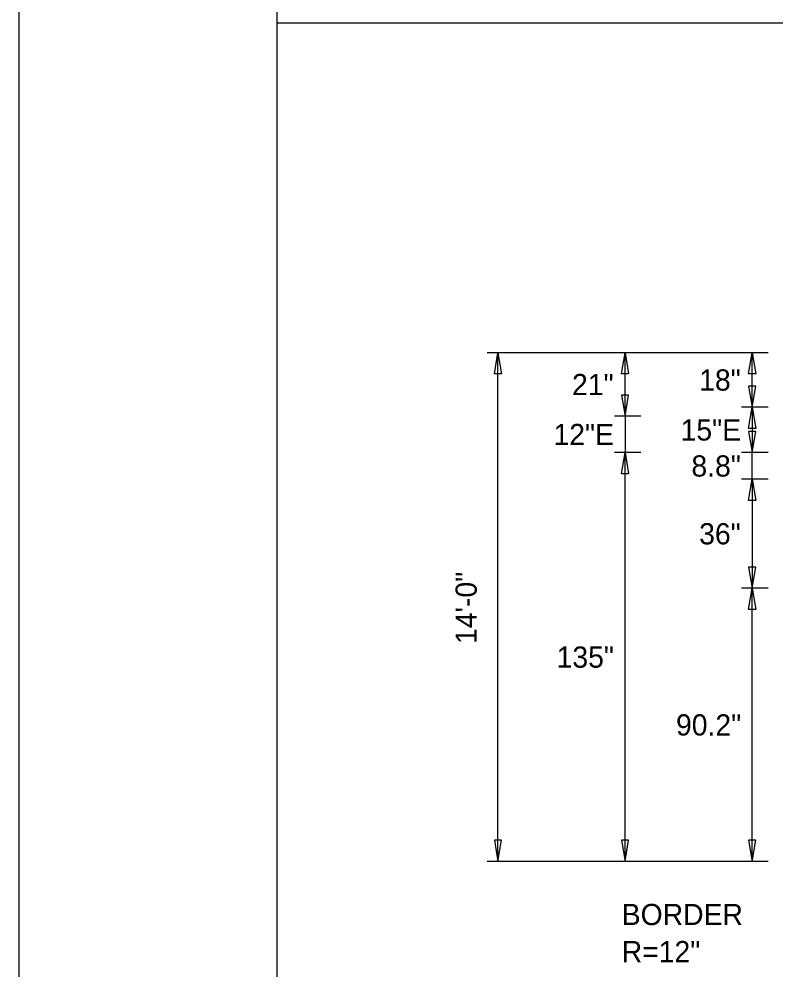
# Model space of a CAD drawing. Extents: x 2150010 to 2150174, y 145114 to 145224.
# Drawn here: x 2150010.46 to 2150031.3, y 145140.9 to 145167.07 of the extents above; entities that cross this region are included whole.
import ezdxf

# ---------------------------------------------------------------- set-up
doc = ezdxf.new("R2010")
doc.units = 0
for name, color, linetype in [('BORDER', 7, 'Continuous'), ('GSDIMS', 7, 'Continuous'), ('Level 1', 7, 'Continuous'), ('PDF', 7, 'Continuous')]:
    doc.layers.add(name, color=color, linetype=linetype)

msp = doc.modelspace()

# ---------------------------------------------------------------- linework, layer by layer
at = {"layer": 'BORDER'}
for p, q in [((2150010.458, 145219.948), (2150010.458, 145114.088)), ((2150017.557, 145216.512), (2150017.557, 145117.388))]:
    msp.add_line(p, q, dxfattribs=at)
at = {"layer": 'GSDIMS'}
for p, q in [((2150024.083, 145157.883), (2150023.353, 145157.883)), ((2150023.645, 145143.883), (2150023.645, 145157.883)), ((2150031.083, 145157.883), (2150024.083, 145157.883)), ((2150027.583, 145157.883), (2150026.853, 145157.883)), ((2150027.145, 145156.133), (2150027.145, 145157.883)), ((2150031.083, 145157.883), (2150030.353, 145157.883)), ((2150030.645, 145156.383), (2150030.645, 145157.883)), ((2150031.083, 145156.383), (2150030.353, 145156.383)), ((2150031.083, 145156.383), (2150030.353, 145156.383)), ((2150030.645, 145156.383), (2150030.645, 145155.133)), ((2150027.583, 145156.133), (2150026.853, 145156.133)), ((2150027.583, 145156.133), (2150026.853, 145156.133)), ((2150027.145, 145156.133), (2150027.145, 145155.133)), ((2150027.583, 145155.133), (2150026.853, 145155.133)), ((2150027.583, 145155.133), (2150026.853, 145155.133)), ((2150027.145, 145143.883), (2150027.145, 145155.133)), ((2150031.083, 145155.133), (2150030.353, 145155.133)), ((2150031.083, 145155.133), (2150030.353, 145155.133)), ((2150030.645, 145154.401), (2150030.645, 145155.133)), ((2150031.083, 145154.401), (2150030.353, 145154.401)), ((2150031.083, 145154.401), (2150030.353, 145154.401)), ((2150030.645, 145154.401), (2150030.645, 145151.401)), ((2150031.083, 145151.401), (2150030.353, 145151.401)), ((2150031.083, 145151.401), (2150030.353, 145151.401)), ((2150030.645, 145143.883), (2150030.645, 145151.401)), ((2150024.083, 145143.883), (2150023.353, 145143.883)), ((2150031.083, 145143.883), (2150024.083, 145143.883)), ((2150027.583, 145143.883), (2150026.853, 145143.883)), ((2150031.083, 145143.883), (2150030.353, 145143.883))]:
    msp.add_line(p, q, dxfattribs=at)
for points in [[(2150023.645, 145157.883), (2150023.742, 145157.3), (2150023.548, 145157.3)], [(2150027.145, 145157.883), (2150027.242, 145157.3), (2150027.048, 145157.3)], [(2150030.645, 145157.883), (2150030.742, 145157.3), (2150030.548, 145157.3)], [(2150030.645, 145156.383), (2150030.742, 145156.966), (2150030.548, 145156.966)], [(2150027.145, 145156.133), (2150027.242, 145156.716), (2150027.048, 145156.716)], [(2150030.645, 145156.383), (2150030.742, 145155.8), (2150030.548, 145155.8)], [(2150030.645, 145155.133), (2150030.742, 145155.716), (2150030.548, 145155.716)], [(2150027.145, 145155.133), (2150027.242, 145154.55), (2150027.048, 145154.55)], [(2150030.645, 145154.401), (2150030.742, 145153.818), (2150030.548, 145153.818)], [(2150030.645, 145151.401), (2150030.742, 145151.984), (2150030.548, 145151.984)], [(2150030.645, 145151.401), (2150030.742, 145150.818), (2150030.548, 145150.818)], [(2150023.645, 145143.883), (2150023.742, 145144.466), (2150023.548, 145144.466)], [(2150027.145, 145143.883), (2150027.242, 145144.466), (2150027.048, 145144.466)], [(2150030.645, 145143.883), (2150030.742, 145144.466), (2150030.548, 145144.466)]]:
    msp.add_lwpolyline(points, close=True, dxfattribs=at)
at = {"layer": 'Level 1'}
msp.add_line((2150135.447, 145166.95), (2150017.557, 145166.95), dxfattribs=at)
at = {"layer": 'PDF'}
msp.add_lwpolyline([(2150010.458, 145114.088), (2150174.061, 145114.088), (2150174.061, 145219.948), (2150010.458, 145219.948)], close=True, dxfattribs=at)

# ---------------------------------------------------------------- texts
at = {"layer": 'GSDIMS'}
for s, p in [('18"', (2150029.186, 145156.841)), ('21"', (2150025.686, 145156.716)), ('15"E', (2150028.675, 145155.466)), ('12"E', (2150025.175, 145155.341)), ('8.8"', (2150028.973, 145154.475)), ('36"', (2150029.186, 145152.609)), ('135"', (2150025.261, 145149.216)), ('90.2"', (2150028.549, 145147.35)), ('BORDER', (2150027.054, 145142.133)), ('R=12"', (2150027.054, 145141.112))]:
    msp.add_text(s, height=0.5833, dxfattribs=at).set_placement(p)
msp.add_text('14\'-0"', height=0.5833, rotation=90, dxfattribs=at).set_placement((2150023.062, 145149.869))

doc.saveas('drawing.dxf')
